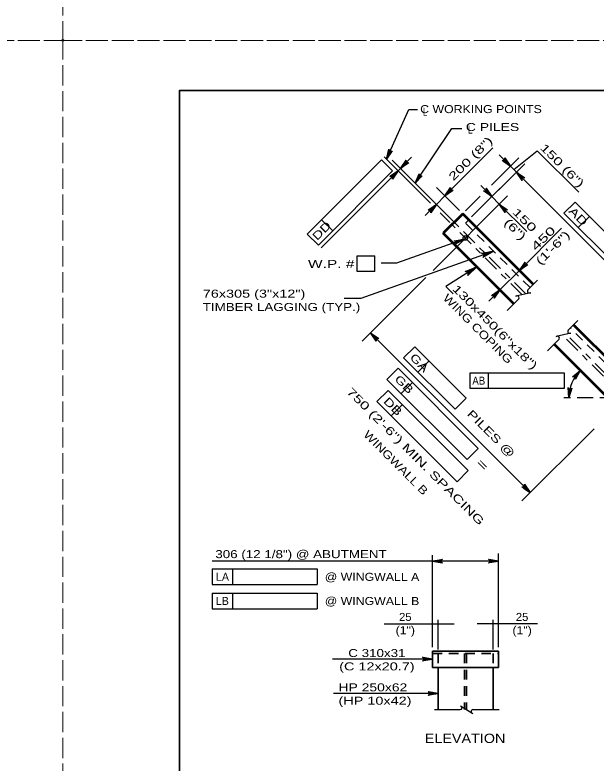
# Model space of a CAD drawing. Extents: x -6.4 to 73.1, y -66 to 0.
# Drawn here: x 33.28 to 42, y -54.84 to -43.62 of the extents above; entities that cross this region are included whole.
import ezdxf
from ezdxf.enums import TextEntityAlignment as Align

# ---------------------------------------------------------------- set-up
doc = ezdxf.new("R2010")
doc.units = 0
doc.header["$LTSCALE"] = 0.048
doc.header["$PDMODE"] = 32
doc.header["$PDSIZE"] = 0.024
for name, pattern in [('DOT_DASHED', [7.7, 5, -1.2, 0.3, -1.2]), ('LONG_DASHED', [7.5, 6, -1.5]), ('MEDIUM_DASHED', [4.5, 3, -1.5])]:
    doc.linetypes.add(name, pattern=pattern)
for name, color, linetype, lineweight in [('1', 7, 'Continuous', 13), ('2', 7, 'Continuous', 53), ('3', 7, 'Continuous', 35), ('4', 7, 'Continuous', 25), ('5', 7, 'Continuous', 25), ('63', 7, 'LONG_DASHED', 13), ('8', 7, 'Continuous', 25)]:
    doc.layers.add(name, color=color, linetype=linetype, lineweight=lineweight)
doc.layers.add('62', color=7, linetype='Continuous')

msp = doc.modelspace()

# ---------------------------------------------------------------- hatches: boundary and pattern name
at = {"layer": '4'}
for points in [[(38.85533, -45.78175), (38.91267, -45.678), (38.89475, -45.67)], [(39.13342, -45.823), (39.16125, -45.85083), (39.06375, -45.92042)], [(40.64458, -45.78775), (40.61675, -45.81558), (40.71417, -45.88517)], [(38.9315, -46.02492), (38.95933, -46.05275), (39.02892, -45.95533)], [(40.90208, -46.04525), (40.87425, -46.07308), (40.80467, -45.97567)], [(39.28492, -46.14158), (39.359, -46.04908), (39.34267, -46.03808)], [(39.80133, -46.236), (39.82917, -46.26383), (39.73175, -46.33342)], [(40.36692, -46.24642), (40.33908, -46.27425), (40.4365, -46.34383)], [(39.50683, -46.5305), (39.53467, -46.55833), (39.60425, -46.46092)], [(40.64525, -46.52475), (40.61742, -46.55267), (40.54783, -46.45517)], [(40.0205, -46.98258), (39.90592, -47.01292), (39.9125, -47.03142)], [(40.46458, -47.16367), (40.35, -47.194), (40.35658, -47.2125)], [(40.91842, -47.35308), (40.94625, -47.38092), (40.84883, -47.4505)], [(40.45908, -47.81242), (40.48692, -47.84025), (40.5565, -47.74283)], [(38.71225, -48.45783), (38.68442, -48.48567), (38.61483, -48.38825)], [(40.9405, -50.686), (40.91267, -50.71392), (41.01008, -50.7835)]]:
    msp.add_hatch(color=256, dxfattribs=at).paths.add_polyline_path(points)

# ---------------------------------------------------------------- linework, layer by layer
at = {"layer": '1', "lineweight": 35}
msp.add_lwpolyline([(35.75, -65.25), (67.25, -65.25), (67.25, -44.75), (35.75, -44.75)], close=True, dxfattribs=at)
at = {"layer": '2'}
for p, q in [((39.99883, -46.6005), (39.7065, -46.89283)), ((41.05867, -47.66042), (39.99883, -46.6005)), ((40.76642, -47.95267), (39.7065, -46.89283)), ((42.463, -49.06467), (41.66308, -48.26483)), ((42.29175, -49.47808), (41.37083, -48.55708))]:
    msp.add_line(p, q, dxfattribs=at)
at = {"layer": '3'}
for p, q in [((40.08933, -46.691), (40.04058, -46.73975)), ((39.54658, -53.1625), (39.54658, -53.4085)), ((39.54658, -53.1625), (40.53625, -53.1625)), ((40.53625, -53.4085), (40.53625, -53.1625)), ((39.54658, -53.4085), (40.53625, -53.4085)), ((39.62858, -53.4085), (39.62858, -54.03725)), ((40.45425, -54.03725), (40.45425, -53.4085))]:
    msp.add_line(p, q, dxfattribs=at)
at = {"layer": '3', "linetype": 'MEDIUM_DASHED'}
for p, q in [((41.01, -47.70908), (40.04058, -46.73975)), ((42.6585, -49.36), (41.61442, -48.3135)), ((39.54658, -53.19692), (40.53625, -53.19692)), ((39.62858, -53.19692), (39.62858, -53.4085)), ((40.02767, -53.19692), (40.02767, -54.03725)), ((40.05517, -53.19692), (40.05517, -54.03725)), ((40.45425, -53.19692), (40.45425, -53.4085))]:
    msp.add_line(p, q, dxfattribs=at)
at = {"layer": '3', "lineweight": 25}
for p, q in [((39.57525, -54.03725), (39.96233, -54.03725)), ((39.96442, -53.97917), (40.14917, -54.09533)), ((40.14875, -54.03725), (40.54425, -54.03725))]:
    msp.add_line(p, q, dxfattribs=at)
for centre, start, end in [((39.96229, -54.00999), 270, 60), ((40.1513, -54.06442), 95.32859, 237.86724)]:
    msp.add_arc(centre, 0.02728, start, end, dxfattribs=at)
at = {"layer": '4'}
for p, q in [((38.85533, -45.78175), (39.1905, -45.03567)), ((39.1905, -45.03567), (39.32275, -45.03567)), ((39.28492, -46.14158), (39.83758, -45.31983)), ((39.83758, -45.31983), (39.98783, -45.31983)), ((39.73175, -46.33342), (40.45208, -45.61308)), ((40.76667, -45.93775), (41.1175, -45.655)), ((41.1175, -45.655), (41.74075, -46.27808)), ((39.514, -46.44042), (38.82283, -45.74917)), ((39.06383, -45.92042), (39.23083, -45.75342)), ((40.42958, -46.16975), (40.8395, -45.75992)), ((40.80467, -45.97567), (40.54717, -45.71817)), ((37.66708, -46.90475), (38.78067, -45.79117)), ((38.78067, -45.79117), (38.94767, -45.95825)), ((39.86008, -46.71675), (38.9385, -45.79517)), ((40.13283, -46.6475), (40.92992, -45.85042)), ((40.71417, -45.88517), (40.60975, -45.78083)), ((37.83417, -47.07183), (38.94767, -45.95825)), ((39.02892, -45.95533), (37.87325, -47.11092)), ((39.06375, -45.92042), (39.02892, -45.95533)), ((43.17833, -48.34933), (40.80467, -45.97567)), ((40.916, -46.087), (40.9995, -46.17058)), ((39.951, -46.55267), (39.6065, -46.20817)), ((40.13283, -46.6475), (40.56175, -46.21858)), ((40.4365, -46.34383), (40.2695, -46.17683)), ((40.67308, -46.32992), (39.55342, -47.44967)), ((39.60425, -46.46092), (39.73175, -46.33342)), ((40.04242, -46.557), (40.26225, -46.33708)), ((40.4365, -46.34383), (40.54783, -46.45517)), ((41.68517, -46.42617), (41.51817, -46.59317)), ((41.68517, -46.42617), (42.88783, -47.62883)), ((39.60425, -46.46092), (39.43725, -46.62792)), ((40.54783, -46.45517), (40.95908, -46.8665)), ((39.806, -46.73242), (39.66275, -46.58908)), ((41.51817, -46.59317), (42.72075, -47.79583)), ((41.899, -46.64), (41.732, -46.80708)), ((37.881, -46.69092), (38.048, -46.85792)), ((40.84883, -47.4505), (41.48333, -46.81583)), ((37.66708, -46.90475), (37.83417, -47.07183)), ((38.41617, -47.23067), (38.67983, -47.23067)), ((38.41617, -47.46683), (38.41617, -47.23067)), ((38.67983, -47.46683), (38.67983, -47.23067)), ((40.5565, -47.74283), (40.84883, -47.4505)), ((40.83125, -47.43292), (40.97408, -47.57575)), ((38.67983, -47.46683), (38.41617, -47.46683)), ((39.44642, -47.55667), (38.48958, -48.5135)), ((40.5565, -47.74283), (40.3895, -47.90983)), ((40.53892, -47.72525), (40.68175, -47.86808)), ((41.01008, -50.7835), (38.61483, -48.38825)), ((39.27933, -48.59475), (39.11233, -48.76183)), ((39.27933, -48.59475), (40.05117, -49.36667)), ((39.11233, -48.76183), (39.88417, -49.53367)), ((39.02983, -48.91725), (38.86283, -49.08425)), ((39.02983, -48.91725), (40.2325, -50.11992)), ((39.49317, -48.80867), (39.32617, -48.97567)), ((40.11008, -48.98733), (41.52208, -48.98733)), ((40.11008, -49.22358), (40.11008, -48.98733)), ((40.38383, -49.22358), (40.38383, -48.98733)), ((41.52208, -48.98733), (41.52208, -49.22358)), ((38.86283, -49.08425), (40.06542, -50.28692)), ((39.24367, -49.13108), (39.07667, -49.29817)), ((38.87875, -49.25075), (38.71175, -49.41775)), ((38.87875, -49.25075), (40.08142, -50.45333)), ((41.52208, -49.22358), (40.11008, -49.22358)), ((40.05117, -49.36667), (39.88417, -49.53367)), ((38.71175, -49.41775), (39.91442, -50.62042)), ((39.09267, -49.46458), (38.92558, -49.63158)), ((41.96892, -49.82475), (40.88492, -50.90875)), ((40.2325, -50.11992), (40.06542, -50.28692)), ((40.08142, -50.45333), (39.91442, -50.62042)), ((39.54658, -53.1025), (39.54658, -51.7235)), ((40.53625, -53.1025), (40.53625, -51.69858)), ((39.54658, -51.81067), (36.242, -51.81067)), ((40.53625, -51.81067), (39.54658, -51.81067)), ((36.242, -51.92758), (37.81683, -51.92758)), ((36.242, -51.92758), (36.242, -52.16375)), ((36.5445, -51.92758), (36.5445, -52.16375)), ((37.81683, -51.92758), (37.81683, -52.16375)), ((36.242, -52.16375), (37.81683, -52.16375)), ((36.242, -52.29), (37.81683, -52.29)), ((36.242, -52.29), (36.242, -52.52625)), ((36.5445, -52.29), (36.5445, -52.52625)), ((37.81683, -52.29), (37.81683, -52.52625)), ((36.242, -52.52625), (37.81683, -52.52625)), ((39.62858, -53.13692), (39.62858, -52.68983)), ((40.45425, -53.13692), (40.45425, -52.68983)), ((38.82233, -52.74983), (39.86858, -52.74983)), ((41.12083, -52.74983), (40.21425, -52.74983)), ((39.54658, -53.28025), (38.04742, -53.28025)), ((39.62858, -53.79733), (38.06058, -53.79733))]:
    msp.add_line(p, q, dxfattribs=at)
at = {"layer": '4', "linetype": 'DOT_DASHED'}
for p, q in [((40.88908, -47.81542), (39.84458, -46.77092)), ((40.94592, -47.8025), (39.87142, -46.728)), ((42.49058, -49.417), (41.49325, -48.41967)), ((42.53958, -49.39617), (41.55, -48.40667)), ((53.29392, -49.36), (41.48717, -49.36))]:
    msp.add_line(p, q, dxfattribs=at)
at = {"layer": '4'}
for points in [[(38.85533, -45.78175), (38.89092, -45.63425), (38.8935, -45.648), (38.90017, -45.6575), (38.90858, -45.66317), (38.91842, -45.66567), (38.93, -45.66442), (38.94192, -45.65717), (38.85533, -45.78175), (38.93, -45.66442), (38.91842, -45.66567), (38.85533, -45.78175), (38.90858, -45.66317), (38.90017, -45.6575), (38.85533, -45.78175), (38.8935, -45.648)], [(40.71417, -45.88517), (40.58892, -45.7995), (40.60267, -45.802), (40.61392, -45.79917), (40.62217, -45.79325), (40.62808, -45.785), (40.63092, -45.77375), (40.62842, -45.76), (40.71417, -45.88517), (40.63092, -45.77375), (40.62808, -45.785), (40.71417, -45.88517), (40.62217, -45.79325), (40.61392, -45.79917), (40.71417, -45.88517), (40.60267, -45.802)], [(39.06383, -45.92042), (39.1495, -45.79517), (39.147, -45.80892), (39.14992, -45.82025), (39.15575, -45.8285), (39.164, -45.83433), (39.17533, -45.83725), (39.18908, -45.83475), (39.06383, -45.92042), (39.17533, -45.83725), (39.164, -45.83433), (39.06383, -45.92042), (39.15575, -45.8285), (39.14992, -45.82025), (39.06383, -45.92042), (39.147, -45.80892)], [(39.02892, -45.95533), (38.94325, -46.08058), (38.94575, -46.06683), (38.94283, -46.0555), (38.937, -46.04725), (38.92867, -46.04142), (38.91742, -46.0385), (38.90367, -46.041), (39.02892, -45.95533), (38.91742, -46.0385), (38.92867, -46.04142), (39.02892, -45.95533), (38.937, -46.04725), (38.94283, -46.0555), (39.02892, -45.95533), (38.94575, -46.06683)], [(39.28492, -46.14158), (39.34492, -46.00225), (39.34517, -46.01625), (39.35017, -46.02667), (39.3575, -46.03375), (39.36675, -46.03783), (39.37833, -46.0385), (39.39133, -46.03342), (39.28492, -46.14158), (39.37833, -46.0385), (39.36675, -46.03783), (39.28492, -46.14158), (39.3575, -46.03375), (39.35017, -46.02667), (39.28492, -46.14158), (39.34517, -46.01625)], [(40.80467, -45.97567), (40.92992, -46.06133), (40.91617, -46.05883), (40.90483, -46.06175), (40.89658, -46.06758), (40.89075, -46.07583), (40.88783, -46.08717), (40.89033, -46.10092), (40.80467, -45.97567), (40.88783, -46.08717), (40.89075, -46.07583), (40.80467, -45.97567), (40.89658, -46.06758), (40.90483, -46.06175), (40.80467, -45.97567), (40.91617, -46.05883)], [(39.73175, -46.33342), (39.81742, -46.20817), (39.81492, -46.22192), (39.81783, -46.23325), (39.82367, -46.2415), (39.83192, -46.24733), (39.84325, -46.25025), (39.857, -46.24775), (39.73175, -46.33342), (39.84325, -46.25025), (39.83192, -46.24733), (39.73175, -46.33342), (39.82367, -46.2415), (39.81783, -46.23325), (39.73175, -46.33342), (39.81492, -46.22192)], [(40.4365, -46.34383), (40.31125, -46.25817), (40.325, -46.26067), (40.33633, -46.25775), (40.34458, -46.25192), (40.35042, -46.24367), (40.35333, -46.23233), (40.35083, -46.21858), (40.4365, -46.34383), (40.35333, -46.23233), (40.35042, -46.24367), (40.4365, -46.34383), (40.34458, -46.25192), (40.33633, -46.25775), (40.4365, -46.34383), (40.325, -46.26067)], [(39.60425, -46.46092), (39.51858, -46.58617), (39.52108, -46.57242), (39.51817, -46.56108), (39.51233, -46.55283), (39.50408, -46.547), (39.49275, -46.54408), (39.479, -46.54658), (39.60425, -46.46092), (39.49275, -46.54408), (39.50408, -46.547), (39.60425, -46.46092), (39.51233, -46.55283), (39.51817, -46.56108), (39.60425, -46.46092), (39.52108, -46.57242)], [(40.54783, -46.45517), (40.67308, -46.54083), (40.65933, -46.53833), (40.648, -46.54125), (40.63975, -46.54708), (40.63392, -46.55542), (40.631, -46.56667), (40.6335, -46.58042), (40.54783, -46.45517), (40.631, -46.56667), (40.63392, -46.55542), (40.54783, -46.45517), (40.63975, -46.54708), (40.648, -46.54125), (40.54783, -46.45517), (40.65933, -46.53833)], [(40.0205, -46.98258), (39.00667, -47.3435), (38.7745, -47.3435)], [(40.0205, -46.98258), (39.88942, -47.05892), (39.8975, -47.04758), (39.89975, -47.03617), (39.898, -47.02617), (39.89308, -47.01733), (39.88408, -47.00992), (39.87067, -47.00625), (40.0205, -46.98258), (39.88408, -47.00992), (39.89308, -47.01733), (40.0205, -46.98258), (39.898, -47.02617), (39.89975, -47.03617), (40.0205, -46.98258), (39.8975, -47.04758)], [(40.46458, -47.16367), (38.47175, -47.87208), (38.21833, -47.87208)], [(40.46458, -47.16367), (40.30067, -47.259), (40.31083, -47.24483), (40.31367, -47.23058), (40.3115, -47.21808), (40.30525, -47.207), (40.29408, -47.19775), (40.27725, -47.19317), (40.46458, -47.16367), (40.29408, -47.19775), (40.30525, -47.207), (40.46458, -47.16367), (40.3115, -47.21808), (40.31367, -47.23058), (40.46458, -47.16367), (40.31083, -47.24483)], [(40.84883, -47.4505), (40.9345, -47.32525), (40.932, -47.339), (40.93492, -47.35025), (40.94075, -47.35858), (40.949, -47.36442), (40.96033, -47.36733), (40.97408, -47.36483), (40.84883, -47.4505), (40.96033, -47.36733), (40.949, -47.36442), (40.84883, -47.4505), (40.94075, -47.35858), (40.93492, -47.35025), (40.84883, -47.4505), (40.932, -47.339)], [(40.21258, -47.39892), (39.745, -47.69167), (39.85608, -47.80267)], [(40.21258, -47.39892), (40.07317, -47.5275), (40.08, -47.51142), (40.07967, -47.49692), (40.07483, -47.48517), (40.06642, -47.47567), (40.0535, -47.469), (40.036, -47.46825), (40.21258, -47.39892), (40.0535, -47.469), (40.06642, -47.47567), (40.21258, -47.39892), (40.07483, -47.48517), (40.07967, -47.49692), (40.21258, -47.39892), (40.08, -47.51142)], [(40.5565, -47.74283), (40.47083, -47.86808), (40.47333, -47.85433), (40.47042, -47.843), (40.46458, -47.83475), (40.45633, -47.82892), (40.445, -47.826), (40.43125, -47.8285), (40.5565, -47.74283), (40.445, -47.826), (40.45633, -47.82892), (40.5565, -47.74283), (40.46458, -47.83475), (40.47042, -47.843), (40.5565, -47.74283), (40.47333, -47.85433)], [(38.61483, -48.38825), (38.74008, -48.47392), (38.72633, -48.47142), (38.715, -48.47433), (38.70675, -48.48017), (38.70092, -48.48842), (38.698, -48.49975), (38.7005, -48.5135), (38.61483, -48.38825), (38.698, -48.49975), (38.70092, -48.48842), (38.61483, -48.38825), (38.70675, -48.48017), (38.715, -48.47433), (38.61483, -48.38825), (38.72633, -48.47142)], [(41.76292, -48.94917), (41.69108, -49.08283), (41.69217, -49.06892), (41.688, -49.058), (41.68133, -49.05033), (41.67242, -49.0455), (41.66092, -49.04375), (41.6475, -49.04775), (41.76292, -48.94917), (41.66092, -49.04375), (41.67242, -49.0455), (41.76292, -48.94917), (41.68133, -49.05033), (41.688, -49.058), (41.76292, -48.94917), (41.69217, -49.06892)], [(41.59275, -49.36), (41.58067, -49.20867), (41.58742, -49.221), (41.59675, -49.22792), (41.6065, -49.23075), (41.61667, -49.23008), (41.62725, -49.22525), (41.63633, -49.21467), (41.59275, -49.36), (41.62725, -49.22525), (41.61667, -49.23008), (41.59275, -49.36), (41.6065, -49.23075), (41.59675, -49.22792), (41.59275, -49.36), (41.58742, -49.221)], [(41.01008, -50.7835), (40.88483, -50.69783), (40.89858, -50.70033), (40.90992, -50.69742), (40.91817, -50.69158), (40.924, -50.68333), (40.92692, -50.672), (40.92442, -50.65825), (41.01008, -50.7835), (40.92692, -50.672), (40.924, -50.68333), (41.01008, -50.7835), (40.91817, -50.69158), (40.90992, -50.69742), (41.01008, -50.7835), (40.89858, -50.70033)], [(39.54658, -51.81067), (39.69575, -51.78267), (39.69, -51.78667), (39.68425, -51.79067), (39.68125, -51.79567), (39.67833, -51.80067), (39.67742, -51.80567), (39.67658, -51.81067), (39.67742, -51.81567), (39.67833, -51.82067), (39.68125, -51.82567), (39.68425, -51.83067), (39.69, -51.83467), (39.69575, -51.83867), (39.54658, -51.81067), (39.69, -51.83467), (39.68425, -51.83067), (39.54658, -51.81067), (39.68125, -51.82567), (39.67833, -51.82067), (39.54658, -51.81067), (39.67742, -51.81567), (39.67658, -51.81067), (39.54658, -51.81067), (39.67742, -51.80567), (39.67833, -51.80067), (39.54658, -51.81067), (39.68125, -51.79567), (39.68425, -51.79067), (39.54658, -51.81067), (39.69, -51.78667)], [(40.53625, -51.81067), (40.38708, -51.83867), (40.39283, -51.83467), (40.39858, -51.83067), (40.40158, -51.82567), (40.4045, -51.82067), (40.40542, -51.81567), (40.40625, -51.81067), (40.40542, -51.80567), (40.4045, -51.80067), (40.40158, -51.79567), (40.39858, -51.79067), (40.39283, -51.78667), (40.38708, -51.78267), (40.53625, -51.81067), (40.39283, -51.78667), (40.39858, -51.79067), (40.53625, -51.81067), (40.40158, -51.79567), (40.4045, -51.80067), (40.53625, -51.81067), (40.40542, -51.80567), (40.40625, -51.81067), (40.53625, -51.81067), (40.40542, -51.81567), (40.4045, -51.82067), (40.53625, -51.81067), (40.40158, -51.82567), (40.39858, -51.83067), (40.53625, -51.81067), (40.39283, -51.83467)], [(39.54658, -53.28025), (39.39742, -53.30825), (39.40317, -53.30425), (39.40892, -53.30025), (39.41192, -53.29525), (39.41483, -53.29025), (39.41575, -53.28525), (39.41658, -53.28025), (39.41575, -53.27525), (39.41483, -53.27025), (39.41192, -53.26525), (39.40892, -53.26025), (39.40317, -53.25625), (39.39742, -53.25233), (39.54658, -53.28025), (39.40317, -53.25625), (39.40892, -53.26025), (39.54658, -53.28025), (39.41192, -53.26525), (39.41483, -53.27025), (39.54658, -53.28025), (39.41575, -53.27525), (39.41658, -53.28025), (39.54658, -53.28025), (39.41575, -53.28525), (39.41483, -53.29025), (39.54658, -53.28025), (39.41192, -53.29525), (39.40892, -53.30025), (39.54658, -53.28025), (39.40317, -53.30425)], [(39.62858, -53.79733), (39.47942, -53.82533), (39.48517, -53.82133), (39.49092, -53.81733), (39.49392, -53.81233), (39.49683, -53.80733), (39.49775, -53.80233), (39.49858, -53.79733), (39.49775, -53.79233), (39.49683, -53.78733), (39.49392, -53.78233), (39.49092, -53.77733), (39.48517, -53.77333), (39.47942, -53.76942), (39.62858, -53.79733), (39.48517, -53.77333), (39.49092, -53.77733), (39.62858, -53.79733), (39.49392, -53.78233), (39.49683, -53.78733), (39.62858, -53.79733), (39.49775, -53.79233), (39.49858, -53.79733), (39.62858, -53.79733), (39.49775, -53.80233), (39.49683, -53.80733), (39.62858, -53.79733), (39.49392, -53.81233), (39.49092, -53.81733), (39.62858, -53.79733), (39.48517, -53.82133)]]:
    msp.add_lwpolyline(points, dxfattribs=at)
for points in [[(38.85533, -45.78175), (38.91267, -45.678), (38.89475, -45.67)], [(39.13342, -45.823), (39.16125, -45.85083), (39.06375, -45.92042)], [(40.64458, -45.78775), (40.61675, -45.81558), (40.71417, -45.88517)], [(38.9315, -46.02492), (38.95933, -46.05275), (39.02892, -45.95533)], [(40.90208, -46.04525), (40.87425, -46.07308), (40.80467, -45.97567)], [(39.28492, -46.14158), (39.359, -46.04908), (39.34267, -46.03808)], [(39.80133, -46.236), (39.82917, -46.26383), (39.73175, -46.33342)], [(40.36692, -46.24642), (40.33908, -46.27425), (40.4365, -46.34383)], [(39.50683, -46.5305), (39.53467, -46.55833), (39.60425, -46.46092)], [(40.64525, -46.52475), (40.61742, -46.55267), (40.54783, -46.45517)], [(40.0205, -46.98258), (39.90592, -47.01292), (39.9125, -47.03142)], [(40.46458, -47.16367), (40.35, -47.194), (40.35658, -47.2125)], [(40.91842, -47.35308), (40.94625, -47.38092), (40.84883, -47.4505)], [(40.45908, -47.81242), (40.48692, -47.84025), (40.5565, -47.74283)], [(38.71225, -48.45783), (38.68442, -48.48567), (38.61483, -48.38825)], [(40.9405, -50.686), (40.91267, -50.71392), (41.01008, -50.7835)]]:
    msp.add_lwpolyline(points, close=True, dxfattribs=at)
msp.add_circle((40.03835, -46.96472), 0.03402, dxfattribs=at)
msp.add_arc((42.17372, -49.35998), 0.58095, 134.99887, 180.00148, dxfattribs=at)
at = {"layer": '62'}
msp.add_point((34, -44), dxfattribs=at)
at = {"layer": '63'}
for points in [[(0, -44), (34, -44), (34, -22), (0, -22)], [(34, -44), (68, -44), (68, -22), (34, -22)], [(0, -66), (34, -66), (34, -44), (0, -44)], [(34, -66), (68, -66), (68, -44), (34, -44)]]:
    msp.add_lwpolyline(points, close=True, dxfattribs=at)
at = {"layer": '8'}
for p, q in [((41.121, -47.59808), (40.97758, -47.7415)), ((40.84017, -47.87892), (40.66742, -48.05167)), ((41.72575, -48.20217), (41.58233, -48.34558)), ((41.445, -48.48292), (41.27217, -48.65575))]:
    msp.add_line(p, q, dxfattribs=at)
for points in [[(41.005, -47.78908), (41.01875, -47.78583), (40.79717, -47.83642), (40.812, -47.83308)], [(41.60975, -48.39308), (41.6235, -48.38992), (41.40192, -48.44042), (41.41675, -48.43708)]]:
    msp.add_lwpolyline(points, dxfattribs=at)
for centre, start, end in [((40.99768, -47.76162), 135, 285), ((40.81837, -47.86074), 320.32859, 102.86724), ((41.60246, -48.36567), 135, 285), ((41.42314, -48.46479), 320.32859, 102.86724)]:
    msp.add_arc(centre, 0.02841, start, end, dxfattribs=at)

# ---------------------------------------------------------------- texts
at = {"layer": '4'}
for s, width, p in [('C WORKING POINTS', 1.15, (39.36075, -45.09092)), ('L', 0.75, (39.40175, -45.13108)), ('C PILES', 1.3, (40.04608, -45.36)), ('L', 0.75, (40.07942, -45.3985)), ('HP 250x62', 1.3, (38.13492, -53.76408)), ('(HP 10x42)', 1.35, (38.13492, -53.96408))]:
    msp.add_text(s, height=0.12, dxfattribs=dict(at, width=width)).set_placement(p)
for s, rotation, width, p in [('200 (8")', 45, 1.5, (40.15749, -45.81509)), ('AD', 314.938, 1.4, (41.68892, -46.68199)), ('DD', 45, 1.35, (37.92437, -46.89947)), ('GA', 314.938, 1.35, (39.30567, -48.87708)), ('GB', 314.938, 1.35, (39.07767, -49.20158)), ('750 (2\'-6") MIN. SPACING', 315, 1.5, (39.25024, -50.28232)), ('DB', 314.938, 1.4, (38.90892, -49.53291)), ('PILES @', 314.938, 1.4, (40.38322, -49.94149)), ('WINGWALL B', 315, 1.25, (38.95224, -50.37774)), ('=', 314.938, 1.85, (40.25311, -50.40699))]:
    msp.add_text(s, height=0.12, rotation=rotation, dxfattribs=dict(at, width=width)).set_placement(p, align=Align.CENTER)
for s, height, width, p in [('W.P. # ', 0.12, 1.45, (38.05854, -47.41367)), ('AB', 0.12, 0.9, (40.23967, -49.16425)), ('306 (12 1/8") @ ABUTMENT', 0.12, 1.25, (37.5725, -51.76592)), ('25', 0.12, 1.05, (39.13742, -52.7075)), ('25', 0.12, 1.05, (40.88983, -52.7075)), ('(1")', 0.12, 1.15, (39.13742, -52.9075)), ('(1")', 0.12, 1.15, (40.88983, -52.9075)), ('C 310x31', 0.12, 1.25, (38.71146, -53.24942)), ('(C 12x20.7)', 0.12, 1.35, (38.7115, -53.44942)), ('ELEVATION', 0.14, 1.15, (40.03421, -54.53908))]:
    msp.add_text(s, height=height, dxfattribs=dict(at, width=width)).set_placement(p, align=Align.CENTER)
for s, p in [('LA', (36.39429, -52.1055)), ('LB', (36.39187, -52.468))]:
    msp.add_text(s, height=0.12, dxfattribs=at).set_placement(p, align=Align.CENTER)
at = {"layer": '4', "width": 1.15}
for s, p in [('@ WINGWALL A', (37.92958, -52.10558)), ('@ WINGWALL B', (37.92958, -52.468))]:
    msp.add_text(s, height=0.12, rotation=359.938, dxfattribs=at).set_placement(p)
at = {"layer": '5'}
for s, width, p in [('150 (6")', 1.5, (41.14917, -45.61867)), ('130x450(6"x18")', 1.45, (39.833, -47.73583)), ('WING COPING', 1.25, (39.69158, -47.87725))]:
    msp.add_text(s, height=0.12, rotation=315, dxfattribs=dict(at, width=width)).set_placement(p)
for s, rotation, width, p in [('150', 315, 1.6, (40.88449, -46.73532)), ('(6")', 315, 1.5, (40.74316, -46.87682)), ('450', 45, 1.6, (41.25007, -47.01193)), ('(1\'-6")', 45, 1.5, (41.39149, -47.15334))]:
    msp.add_text(s, height=0.12, rotation=rotation, dxfattribs=dict(at, width=width)).set_placement(p, align=Align.CENTER)
for s, width, p in [('76x305 (3"x12")', 1.35, (36.09867, -47.859)), ('TIMBER LAGGING (TYP.)', 1.25, (36.09867, -48.059))]:
    msp.add_text(s, height=0.12, dxfattribs=dict(at, width=width)).set_placement(p)

doc.saveas('drawing.dxf')
